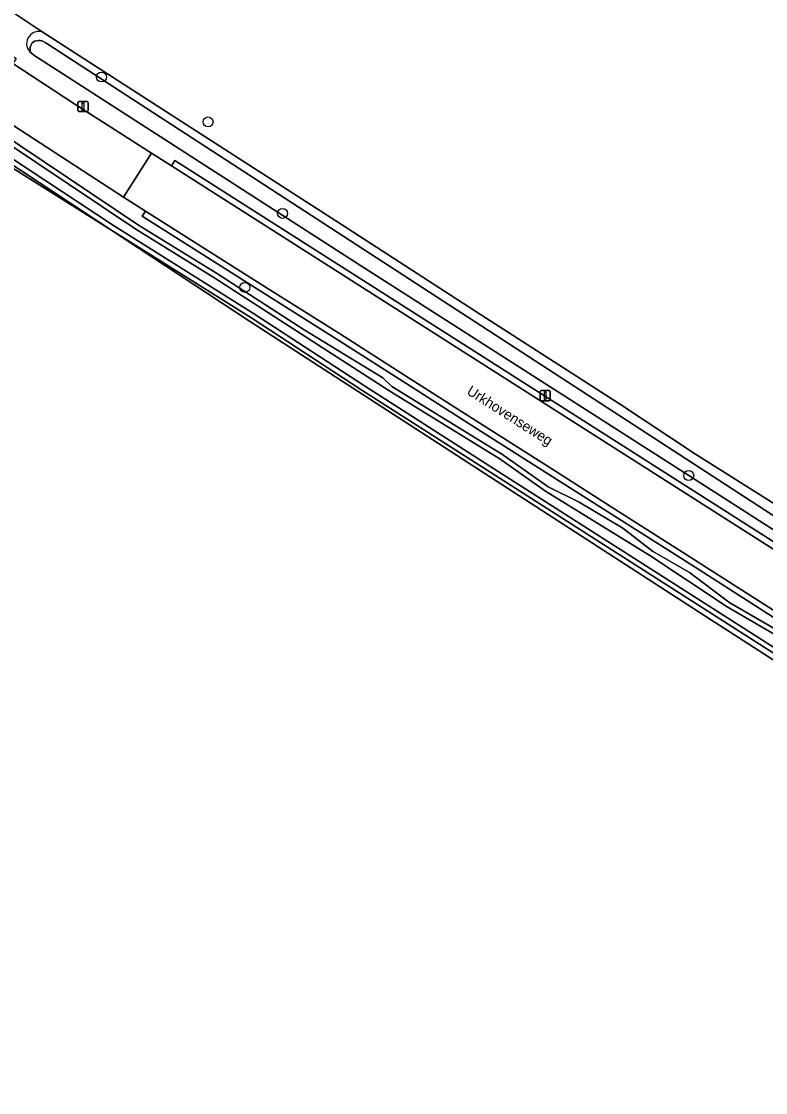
# Model space of a CAD drawing. Extents: x 164494 to 166241, y 382475 to 384495.
# Drawn here: x 165238.2 to 165311.1, y 382865.8 to 382970.6 of the extents above; entities that cross this region are included whole.
import ezdxf

# ---------------------------------------------------------------- set-up
doc = ezdxf.new("R2010")
doc.units = 0
for name, color, linetype in [('IMGEO_Berm_halfverhard', 7, 'Continuous'), ('IMGEO_Boom', 7, 'Continuous'), ('IMGEO_Grasland_agrarisch', 7, 'Continuous'), ('IMGEO_Grasland_overig', 7, 'Continuous'), ('IMGEO_Groenvoorziening', 7, 'Continuous'), ('IMGEO_Hek', 7, 'Continuous'), ('IMGEO_Lichtmast', 7, 'Continuous'), ('IMGEO_Loofbos', 7, 'Continuous'), ('IMGEO_Oever', 7, 'Continuous'), ('IMGEO_Openbare_ruimte_label', 7, 'Continuous'), ('IMGEO_Rijbaan_lokaal_gesloten', 7, 'Continuous'), ('IMGEO_Verkeersbordpaal', 7, 'Continuous'), ('IMGEO_Waterloop', 7, 'Continuous')]:
    doc.layers.add(name, color=color, linetype=linetype)

msp = doc.modelspace()

# ---------------------------------------------------------------- linework, layer by layer
at = {"layer": 'IMGEO_Berm_halfverhard'}
for points in [[(165352.54, 382893.38), (165336.73, 382903.62), (165336.85, 382903.81), (165253.27, 382957.02), (165252.94, 382956.51)], [(165252.94, 382956.51), (165336.52, 382903.3), (165343.27, 382899)], [(165250.4, 382952.08), (165250.07, 382951.57), (165261.99, 382944.04), (165269.08, 382939.56), (165276, 382935.15), (165282.82, 382930.8), (165290.59, 382925.86), (165295.7, 382922.63), (165304.23, 382917.2), (165313.17, 382911.49), (165322.57, 382905.52), (165330.45, 382900.53), (165339.82, 382894.53), (165346.66, 382890.15), (165351.59, 382887)], [(165351.91, 382887.51), (165346.98, 382890.66), (165340.15, 382895.04), (165330.77, 382901.04), (165322.89, 382906.02), (165313.49, 382911.99), (165304.55, 382917.7), (165296.02, 382923.13), (165290.91, 382926.37), (165283.14, 382931.31), (165276.32, 382935.66), (165269.4, 382940.07), (165262.31, 382944.54), (165250.4, 382952.08)]]:
    msp.add_lwpolyline(points, dxfattribs=at)
at = {"layer": 'IMGEO_Boom'}
for centre in [(165246.09, 382965.2), (165256.53, 382960.8), (165263.83, 382951.85), (165260.13, 382944.6), (165303.61, 382926.18)]:
    msp.add_circle(centre, 0.489, dxfattribs=at)
at = {"layer": 'IMGEO_Grasland_agrarisch'}
for points in [[(165284.75, 382925.67), (165260.58, 382941.3), (165247.02, 382950.24), (165226.26, 382963.25), (165218.05, 382968.78), (165207.69, 382978.09), (165193.01, 382990.82), (165177.33, 383004.78), (165162.65, 383018.55), (165156.48, 383024.1), (165142.36, 383037.48)], [(165233.79, 382973.96), (165239.8, 382969.95), (165240.44, 382969.54), (165240.65, 382969.41), (165269.04, 382951.11), (165283.23, 382941.96), (165296.82, 382933.2), (165304.27, 382928.28), (165316.97, 382920.29), (165318.03, 382919.42), (165318.5, 382918.84), (165319.92, 382918.27), (165332.19, 382910.35), (165332.59, 382910.4), (165333.72, 382909.38), (165356.3, 382895.09), (165364.07, 382889.81), (165370.04, 382885.4), (165371.91, 382884.35), (165372.87, 382883.34)], [(165339.77, 382859.26), (165360.03, 382877.2), (165305.75, 382912.08), (165284.75, 382925.67)]]:
    msp.add_lwpolyline(points, dxfattribs=at)
at = {"layer": 'IMGEO_Grasland_overig'}
for points in [[(165240.44, 382969.54), (165239.8, 382969.95), (165233.79, 382973.96), (165232.86, 382974.71), (165232.75, 382974.66), (165231.43, 382974.03), (165229.58, 382974.03), (165227.86, 382974.99), (165218.15, 382982.34), (165206.63, 382993.61), (165197.21, 383002.77), (165186.09, 383013.87), (165174.79, 383024.54), (165168.52, 383030.89), (165169.28, 383031.59)], [(165218.89, 382980.59), (165226.59, 382974.68), (165226.71, 382974.84), (165237.73, 382967.01), (165237.4, 382966.51), (165243.48, 382962.53), (165251, 382957.75), (165252.94, 382956.51), (165253.27, 382957.02), (165336.85, 382903.81), (165336.73, 382903.62), (165352.54, 382893.38)], [(165372.35, 382881.21), (165354.4, 382893.57), (165335.92, 382905.46), (165319.21, 382916.2), (165303.61, 382926.18), (165271.46, 382946.73), (165239.45, 382967.33), (165239.21, 382967.57), (165239.07, 382967.68)]]:
    msp.add_lwpolyline(points, dxfattribs=at)
msp.add_arc((165239.94, 382968.47), 1.18, 65.2376, 221.8655, dxfattribs=at)
at = {"layer": 'IMGEO_Groenvoorziening'}
for points in [[(165215.68, 382974.13), (165233.49, 382961.57), (165249.72, 382950.7), (165257.35, 382945.98), (165265.94, 382940.43), (165273.65, 382935.73), (165274.52, 382934.91), (165284.46, 382928.79), (165285.28, 382928.29), (165289.84, 382925.08), (165292.89, 382923.56), (165297.15, 382921.02), (165300.05, 382918.77), (165303.7, 382916.7), (165307.64, 382913.72)], [(165351.59, 382887), (165346.66, 382890.15), (165339.82, 382894.53), (165330.45, 382900.53), (165322.57, 382905.52), (165313.17, 382911.49), (165304.23, 382917.2), (165295.7, 382922.63), (165290.59, 382925.86), (165282.82, 382930.8), (165276, 382935.15), (165269.08, 382939.56), (165261.99, 382944.04), (165250.07, 382951.57), (165250.4, 382952.08), (165248.25, 382953.45), (165234.66, 382962.25), (165233.03, 382963.43), (165232.68, 382962.94), (165226.08, 382967.71), (165221.45, 382971.07)], [(165307.64, 382913.72), (165312.22, 382911.06), (165319.31, 382906.62), (165321.86, 382904.8), (165327.6, 382901.45), (165332.89, 382897.74), (165336.18, 382895.87), (165347.27, 382888.35), (165359.12, 382880.68), (165360.69, 382879.91), (165364.7, 382877.15), (165363.51, 382875.32), (165369.14, 382871.01), (165370.25, 382872.37), (165378.27, 382865.39), (165382.94, 382860.53), (165382.79, 382860.38), (165383.66, 382859.29), (165383.82, 382859.4), (165390.74, 382849.5)]]:
    msp.add_lwpolyline(points, dxfattribs=at)
at = {"layer": 'IMGEO_Hek'}
for points in [[(165247.02, 382950.24), (165216.96, 382970.05), (165207.69, 382978.09)], [(165284.75, 382925.67), (165260.58, 382941.3), (165247.02, 382950.24)], [(165339.77, 382859.26), (165360.03, 382877.2), (165305.75, 382912.08), (165284.75, 382925.67)]]:
    msp.add_lwpolyline(points, dxfattribs=at)
at = {"layer": 'IMGEO_Lichtmast'}
for p, q in [((165243.78, 382961.91), (165243.78, 382962.71)), ((165243.78, 382962.71), (165243.78, 382961.91)), ((165243.88, 382962.81), (165244.67, 382962.81)), ((165244.67, 382962.81), (165243.88, 382962.81)), ((165244.77, 382962.71), (165244.77, 382961.91)), ((165244.77, 382961.91), (165244.77, 382962.71)), ((165244.67, 382961.81), (165243.88, 382961.81)), ((165243.88, 382961.81), (165244.67, 382961.81))]:
    msp.add_line(p, q, dxfattribs=at)
msp.add_lwpolyline([(165244.2, 382962.68), (165244.35, 382962.68), (165244.35, 382961.93), (165244.2, 382961.93), (165244.2, 382962.68)], dxfattribs=at)
for centre, start, end in [((165243.88, 382962.71), 90, 180), ((165243.88, 382962.71), 90, 180), ((165244.67, 382962.71), 0, 90), ((165244.67, 382962.71), 360, 90), ((165243.88, 382961.91), 180, 270), ((165243.88, 382961.91), 180, 270), ((165244.67, 382961.91), 270, 0), ((165244.67, 382961.91), 270, 0)]:
    msp.add_arc(centre, 0.1, start, end, dxfattribs=at)
at = {"layer": 'IMGEO_Loofbos'}
msp.add_lwpolyline([(165207.69, 382978.09), (165218.05, 382968.78), (165226.26, 382963.25), (165247.02, 382950.24), (165216.96, 382970.05)], close=True, dxfattribs=at)
msp.add_lwpolyline([(165237.15, 382837.43), (165240.67, 382836.81), (165264.01, 382836.63), (165283.57, 382838.17), (165292.87, 382838.64), (165307.64, 382839.37), (165316.68, 382840.98), (165321.12, 382842.04), (165324.33, 382843.63), (165369.14, 382871.01), (165363.51, 382875.32), (165326.65, 382899.4), (165284.7, 382926.17), (165271.58, 382934.54), (165260.73, 382941.64), (165247.02, 382950.24), (165260.58, 382941.3), (165284.75, 382925.67), (165305.75, 382912.08), (165360.03, 382877.2), (165339.77, 382859.26)], dxfattribs=at)
at = {"layer": 'IMGEO_Oever'}
for points in [[(165216.96, 382970.05), (165247.02, 382950.24), (165260.73, 382941.64), (165271.58, 382934.54), (165284.7, 382926.17), (165326.65, 382899.4)], [(165326.91, 382899.81), (165284.96, 382926.58), (165271.84, 382934.95), (165260.99, 382942.05), (165247.28, 382950.65), (165217.25, 382970.44)], [(165372.87, 382883.34), (165371.91, 382884.35), (165370.04, 382885.4), (165364.07, 382889.81), (165356.3, 382895.09), (165333.72, 382909.38), (165332.59, 382910.4), (165332.19, 382910.35), (165319.92, 382918.27), (165318.5, 382918.84), (165318.03, 382919.42), (165316.97, 382920.29), (165304.27, 382928.28), (165296.82, 382933.2), (165283.23, 382941.96), (165269.04, 382951.11), (165240.65, 382969.41), (165240.44, 382969.54)], [(165239.07, 382967.68), (165239.09, 382967.96), (165239.1, 382968.04), (165239.13, 382968.23), (165239.31, 382968.56), (165239.53, 382968.72), (165239.92, 382968.79), (165240.07, 382968.78), (165240.33, 382968.7), (165240.58, 382968.58), (165240.83, 382968.43), (165322.04, 382915.66), (165372.18, 382882.69)], [(165233.21, 382961.17), (165249.46, 382950.3), (165257.09, 382945.57), (165265.68, 382940.02), (165274.23, 382934.52), (165284.2, 382928.38), (165285.01, 382927.88), (165289.59, 382924.66), (165299.79, 382918.36), (165307.37, 382913.32), (165311.97, 382910.64)], [(165312.22, 382911.06), (165307.64, 382913.72), (165303.7, 382916.7), (165300.05, 382918.77), (165297.15, 382921.02), (165292.89, 382923.56), (165289.84, 382925.08), (165285.28, 382928.29), (165284.46, 382928.79), (165274.52, 382934.91), (165273.65, 382935.73), (165265.94, 382940.43), (165257.35, 382945.98), (165249.72, 382950.7), (165233.49, 382961.57)]]:
    msp.add_lwpolyline(points, dxfattribs=at)
msp.add_arc((165239.94, 382968.47), 1.18, 65.2376, 221.8655, dxfattribs=at)
at = {"layer": 'IMGEO_Rijbaan_lokaal_gesloten'}
msp.add_lwpolyline([(165248.25, 382953.45), (165251, 382957.75), (165243.48, 382962.53), (165237.4, 382966.51), (165234.66, 382962.25)], close=True, dxfattribs=at)
msp.add_lwpolyline([(165343.27, 382899), (165336.52, 382903.3), (165252.94, 382956.51), (165251, 382957.75), (165248.25, 382953.45), (165250.4, 382952.08), (165262.31, 382944.54), (165269.4, 382940.07), (165276.32, 382935.66), (165283.14, 382931.31), (165290.91, 382926.37), (165296.02, 382923.13), (165304.55, 382917.7), (165313.49, 382911.99), (165322.89, 382906.02), (165330.77, 382901.04), (165340.15, 382895.04), (165346.98, 382890.66), (165351.91, 382887.51)], dxfattribs=at)
at = {"layer": 'IMGEO_Verkeersbordpaal'}
for p, q in [((165289.06, 382933.6), (165289.06, 382934.4)), ((165289.06, 382934.4), (165289.06, 382933.6)), ((165289.16, 382934.5), (165289.95, 382934.5)), ((165289.95, 382934.5), (165289.16, 382934.5)), ((165290.05, 382934.4), (165290.05, 382933.6)), ((165290.05, 382933.6), (165290.05, 382934.4)), ((165289.95, 382933.5), (165289.16, 382933.5)), ((165289.16, 382933.5), (165289.95, 382933.5))]:
    msp.add_line(p, q, dxfattribs=at)
msp.add_lwpolyline([(165289.48, 382934.38), (165289.63, 382934.38), (165289.63, 382933.63), (165289.48, 382933.63), (165289.48, 382934.38)], dxfattribs=at)
for centre, start, end in [((165289.16, 382934.4), 90, 180), ((165289.16, 382934.4), 90, 180), ((165289.95, 382934.4), 0, 90), ((165289.95, 382934.4), 360, 90), ((165289.16, 382933.6), 180, 270), ((165289.16, 382933.6), 180, 270), ((165289.95, 382933.6), 270, 0), ((165289.95, 382933.6), 270, 0)]:
    msp.add_arc(centre, 0.1, start, end, dxfattribs=at)
at = {"layer": 'IMGEO_Waterloop'}
for points in [[(165217.25, 382970.44), (165247.28, 382950.65), (165260.99, 382942.05), (165271.84, 382934.95), (165284.96, 382926.58), (165326.91, 382899.81)], [(165372.18, 382882.69), (165322.04, 382915.66), (165240.83, 382968.43), (165240.58, 382968.58), (165240.33, 382968.7), (165240.07, 382968.78), (165239.92, 382968.79), (165239.53, 382968.72), (165239.31, 382968.56), (165239.13, 382968.23), (165239.1, 382968.04), (165239.09, 382967.96), (165239.07, 382967.68), (165239.21, 382967.57), (165239.45, 382967.33), (165271.46, 382946.73), (165303.61, 382926.18), (165319.21, 382916.2), (165335.92, 382905.46), (165354.4, 382893.57), (165372.35, 382881.21)], [(165311.97, 382910.64), (165307.37, 382913.32), (165299.79, 382918.36), (165289.59, 382924.66), (165285.01, 382927.88), (165284.2, 382928.38), (165274.23, 382934.52), (165265.68, 382940.02), (165257.09, 382945.57), (165249.46, 382950.3), (165233.21, 382961.17)]]:
    msp.add_lwpolyline(points, dxfattribs=at)

# ---------------------------------------------------------------- texts
at = {"layer": 'IMGEO_Openbare_ruimte_label'}
msp.add_text('Urkhovenseweg', height=1, rotation=327.5024, dxfattribs=at).set_placement((165281.79, 382934.21))

doc.saveas('drawing.dxf')
